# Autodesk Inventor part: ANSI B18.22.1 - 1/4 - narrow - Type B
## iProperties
Comments: To add or edit properties for Autodesk Inventor files, use iProperties.
Created: 2005-06
Part Number: ANSI B18.22.1 - 1/4 - narrow - Type B
Vendor: Autodesk Inc.
Document SubType Name: Modeling
Designer: John Blackburn
Material: Default
Description: Washer B
Standard: ANSI B18.22.1
Size Designation: 1/4 - narrow - Type B
Alert: To add or edit properties for Autodesk Inventor files, use iProperties.
Control State: 0
Master: False
Checked Out: False
Shininess: 64.0
Length Units: 11272
Angle Units: 11279
Time Units: 11290
Mass Units: 11286
Length Display Precision: 3
Angle Display Precision: 2
Compacted: True
Classification: un/spsc 31161807
Density: 0.0
Volumn: 0.0
Area: 0.0
PropertySet Name: Model Information
Author: John Blackburn
Revision Number: 8
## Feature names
1. Body [Extrusion]
